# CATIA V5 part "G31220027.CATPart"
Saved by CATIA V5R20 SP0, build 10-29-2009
Part number: G31220027
Revision: 10
Definition: design
Nomenclature: G31220027
Source: made
Description: NOT SPECIFIED
Bounding box of the stored display mesh (mm): x -8 to 27, y -15.5 to 15.5, z -15.5 to 15.5
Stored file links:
  C:\Users\Raffaele\Desktop\3D X SITO CF\BOLEX\23-BUSH REF 312\G31220027.CATPart

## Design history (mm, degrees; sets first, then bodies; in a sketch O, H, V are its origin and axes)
Body1 "MANIFOLD_SOLID_BREP #8059" (main body)
  Solid1: solid without history
Body2 "MANIFOLD_SOLID_BREP #8202"
  Solid2: solid without history
Body3 "MANIFOLD_SOLID_BREP #8345"
  Solid3: solid without history
Body4 "MANIFOLD_SOLID_BREP #8488"
  Solid4: solid without history
Body5 "MANIFOLD_SOLID_BREP #8631"
  Solid5: solid without history
Body6 "MANIFOLD_SOLID_BREP #8776"
  Solid6: solid without history
Body7 "MANIFOLD_SOLID_BREP #8921"
  Solid7: solid without history
Body8 "MANIFOLD_SOLID_BREP #9066"
  Solid8: solid without history
Body9 "MANIFOLD_SOLID_BREP #9211"
  Solid9: solid without history
Body10 "MANIFOLD_SOLID_BREP #9356"
  Solid10: solid without history
Body11 "MANIFOLD_SOLID_BREP #9501"
  Solid11: solid without history
Body12 "MANIFOLD_SOLID_BREP #9646"
  Solid12: solid without history
Body13 "MANIFOLD_SOLID_BREP #9791"
  Solid13: solid without history
Body14 "MANIFOLD_SOLID_BREP #9936"
  Solid14: solid without history
Body15 "MANIFOLD_SOLID_BREP #10081"
  Solid15: solid without history
Body16 "MANIFOLD_SOLID_BREP #10226"
  Solid16: solid without history
Body17 "MANIFOLD_SOLID_BREP #10371"
  Solid17: solid without history
Body18 "MANIFOLD_SOLID_BREP #10516"
  Solid18: solid without history
Body19 "MANIFOLD_SOLID_BREP #10661"
  Solid19: solid without history
Body20 "MANIFOLD_SOLID_BREP #10806"
  Solid20: solid without history
Body21 "MANIFOLD_SOLID_BREP #10951"
  Solid21: solid without history
Body22 "MANIFOLD_SOLID_BREP #11098"
  Solid22: solid without history
Body23 "MANIFOLD_SOLID_BREP #11243"
  Solid23: solid without history
Body24 "MANIFOLD_SOLID_BREP #11388"
  Solid24: solid without history
Body25 "MANIFOLD_SOLID_BREP #11535"
  Solid25: solid without history
Body26 "MANIFOLD_SOLID_BREP #11680"
  Solid26: solid without history
Body27 "MANIFOLD_SOLID_BREP #11825"
  Solid27: solid without history
Body28 "MANIFOLD_SOLID_BREP #11970"
  Solid28: solid without history
Body29 "MANIFOLD_SOLID_BREP #12115"
  Solid29: solid without history
Body30 "MANIFOLD_SOLID_BREP #12260"
  Solid30: solid without history
Body31 "MANIFOLD_SOLID_BREP #12405"
  Solid31: solid without history
Body32 "MANIFOLD_SOLID_BREP #12548"
  Solid32: solid without history
Body33 "MANIFOLD_SOLID_BREP #12691"
  Solid33: solid without history
Body34 "MANIFOLD_SOLID_BREP #12836"
  Solid34: solid without history
Body35 "MANIFOLD_SOLID_BREP #12981"
  Solid35: solid without history
Body36 "MANIFOLD_SOLID_BREP #13126"
  Solid36: solid without history
Body37 "MANIFOLD_SOLID_BREP #13271"
  Solid37: solid without history
Body38 "MANIFOLD_SOLID_BREP #13418"
  Solid38: solid without history
Body39 "MANIFOLD_SOLID_BREP #13563"
  Solid39: solid without history
Body40 "MANIFOLD_SOLID_BREP #13708"
  Solid40: solid without history
Body41 "MANIFOLD_SOLID_BREP #13855"
  Solid41: solid without history
Body42 "MANIFOLD_SOLID_BREP #14000"
  Solid42: solid without history
Body43 "MANIFOLD_SOLID_BREP #14145"
  Solid43: solid without history
Body44 "MANIFOLD_SOLID_BREP #14290"
  Solid44: solid without history
Body45 "MANIFOLD_SOLID_BREP #14435"
  Solid45: solid without history
Body46 "MANIFOLD_SOLID_BREP #14580"
  Solid46: solid without history
Body47 "MANIFOLD_SOLID_BREP #14725"
  Solid47: solid without history
Body48 "MANIFOLD_SOLID_BREP #14870"
  Solid48: solid without history
Body49 "MANIFOLD_SOLID_BREP #15015"
  Solid49: solid without history
Body50 "MANIFOLD_SOLID_BREP #15160"
  Solid50: solid without history
Body51 "MANIFOLD_SOLID_BREP #15305"
  Solid51: solid without history
Body52 "MANIFOLD_SOLID_BREP #15452"
  Solid52: solid without history
Body53 "MANIFOLD_SOLID_BREP #15597"
  Solid53: solid without history
Body54 "MANIFOLD_SOLID_BREP #15742"
  Solid54: solid without history
Body55 "MANIFOLD_SOLID_BREP #15889"
  Solid55: solid without history
Body56 "MANIFOLD_SOLID_BREP #16032"
  Solid56: solid without history
Body57 "MANIFOLD_SOLID_BREP #16175"
  Solid57: solid without history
